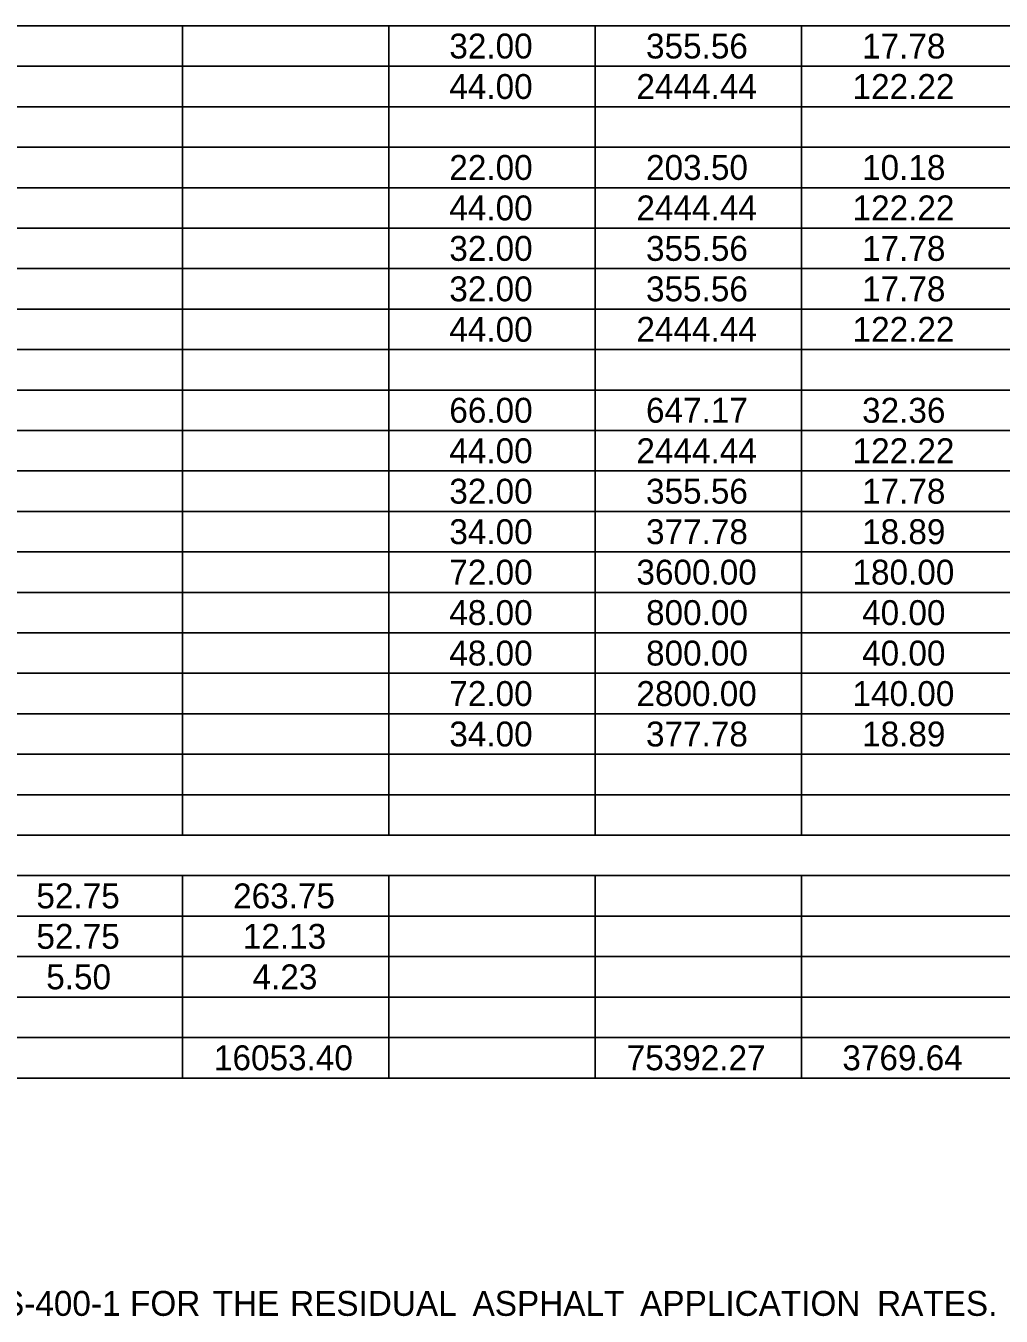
# Model space of a CAD drawing. Extents: x 977434 to 989596, y 1525697 to 1528336.
# Drawn here: x 983038 to 983226, y 1527564.5 to 1527813.2 of the extents above; entities that cross this region are included whole.
import ezdxf

# ---------------------------------------------------------------- set-up
doc = ezdxf.new("R2010")
doc.units = 0
doc.layers.add('Default', color=7, linetype='Continuous')

msp = doc.modelspace()

# ---------------------------------------------------------------- linework, layer by layer
at = {"layer": 'Default'}
for p, q in [((982704.74, 1527813.24), (984062.72, 1527813.24)), ((983068.22, 1527657.24), (983068.22, 1527813.24)), ((983068.22, 1527657.24), (983068.22, 1527813.24)), ((983108, 1527657.24), (983108, 1527813.24)), ((983108, 1527657.24), (983108, 1527813.24)), ((983147.78, 1527657.24), (983147.78, 1527813.24)), ((983147.78, 1527657.24), (983147.78, 1527813.24)), ((983187.56, 1527657.24), (983187.56, 1527813.24)), ((983187.56, 1527657.24), (983187.56, 1527813.24)), ((982704.74, 1527805.44), (984062.72, 1527805.44)), ((982704.74, 1527797.64), (984062.72, 1527797.64)), ((982704.74, 1527789.84), (984062.72, 1527789.84)), ((982704.74, 1527782.04), (984062.72, 1527782.04)), ((982704.74, 1527774.24), (984062.72, 1527774.24)), ((982704.74, 1527766.44), (984062.72, 1527766.44)), ((982704.74, 1527758.64), (984062.72, 1527758.64)), ((982704.74, 1527750.84), (984062.72, 1527750.84)), ((982704.74, 1527743.04), (984062.72, 1527743.04)), ((982704.74, 1527735.24), (984062.72, 1527735.24)), ((982704.74, 1527727.44), (984062.72, 1527727.44)), ((982704.74, 1527719.64), (984062.72, 1527719.64)), ((982704.74, 1527711.84), (984062.72, 1527711.84)), ((982704.74, 1527704.04), (984062.72, 1527704.04)), ((982704.74, 1527696.24), (984062.72, 1527696.24)), ((982704.74, 1527688.44), (984062.72, 1527688.44)), ((982704.74, 1527680.64), (984062.72, 1527680.64)), ((982704.74, 1527672.84), (984062.72, 1527672.84)), ((982704.74, 1527665.04), (984062.72, 1527665.04)), ((982704.74, 1527657.24), (983108, 1527657.24)), ((982704.74, 1527657.24), (984062.72, 1527657.24)), ((983108, 1527657.24), (983346.68, 1527657.24)), ((982704.74, 1527649.44), (984062.72, 1527649.44)), ((983068.22, 1527610.44), (983068.22, 1527649.44)), ((983068.22, 1527610.44), (983068.22, 1527649.44)), ((983108, 1527610.44), (983108, 1527649.44)), ((983108, 1527610.44), (983108, 1527649.44)), ((983147.78, 1527610.44), (983147.78, 1527649.44)), ((983147.78, 1527610.44), (983147.78, 1527649.44)), ((983187.56, 1527610.44), (983187.56, 1527649.44)), ((983187.56, 1527610.44), (983187.56, 1527649.44)), ((982704.74, 1527641.64), (984062.72, 1527641.64)), ((982704.74, 1527633.84), (984062.72, 1527633.84)), ((982704.74, 1527626.04), (984062.72, 1527626.04)), ((982704.74, 1527618.24), (984062.72, 1527618.24)), ((982704.74, 1527610.44), (984062.72, 1527610.44))]:
    msp.add_line(p, q, dxfattribs=at)

# ---------------------------------------------------------------- texts
for s, p in [('32.00', (983119.66, 1527806.94)), ('355.56', (983157.57, 1527806.94)), ('17.78', (983199.21, 1527806.94)), ('44.00', (983119.66, 1527799.14)), ('2444.44', (983155.72, 1527799.14)), ('122.22', (983197.38, 1527799.14)), ('22.00', (983119.66, 1527783.54)), ('203.50', (983157.58, 1527783.54)), ('10.18', (983199.21, 1527783.54)), ('44.00', (983119.66, 1527775.74)), ('2444.44', (983155.72, 1527775.74)), ('122.22', (983197.38, 1527775.74)), ('32.00', (983119.66, 1527767.94)), ('355.56', (983157.57, 1527767.94)), ('17.78', (983199.21, 1527767.94)), ('32.00', (983119.66, 1527760.14)), ('355.56', (983157.57, 1527760.14)), ('17.78', (983199.21, 1527760.14)), ('44.00', (983119.66, 1527752.34)), ('2444.44', (983155.72, 1527752.34)), ('122.22', (983197.38, 1527752.34)), ('66.00', (983119.66, 1527736.74)), ('647.17', (983157.57, 1527736.74)), ('32.36', (983199.21, 1527736.74)), ('44.00', (983119.66, 1527728.94)), ('2444.44', (983155.72, 1527728.94)), ('122.22', (983197.38, 1527728.94)), ('32.00', (983119.66, 1527721.14)), ('355.56', (983157.57, 1527721.14)), ('17.78', (983199.21, 1527721.14)), ('34.00', (983119.66, 1527713.34)), ('377.78', (983157.57, 1527713.34)), ('18.89', (983199.21, 1527713.34)), ('72.00', (983119.66, 1527705.54)), ('3600.00', (983155.72, 1527705.54)), ('180.00', (983197.36, 1527705.54)), ('48.00', (983119.66, 1527697.74)), ('800.00', (983157.58, 1527697.74)), ('40.00', (983199.22, 1527697.74)), ('48.00', (983119.66, 1527689.94)), ('800.00', (983157.58, 1527689.94)), ('40.00', (983199.22, 1527689.94)), ('72.00', (983119.66, 1527682.14)), ('2800.00', (983155.72, 1527682.14)), ('140.00', (983197.36, 1527682.14)), ('34.00', (983119.66, 1527674.34)), ('377.78', (983157.57, 1527674.34)), ('18.89', (983199.21, 1527674.34)), ('52.75', (983040.08, 1527643.14)), ('263.75', (983077.99, 1527643.14)), ('52.75', (983040.08, 1527635.34)), ('12.13', (983079.87, 1527635.34)), ('5.50', (983041.97, 1527627.54)), ('4.23', (983081.74, 1527627.54)), ('16053.40', (983074.3, 1527611.94)), ('75392.27', (983153.84, 1527611.94)), ('3769.64', (983195.41, 1527611.94)), (' SS-400-1', (983027.39, 1527564.6)), (' FOR', (983056.34, 1527564.6)), (' THE', (983072.27, 1527564.6)), (' RESIDUAL', (983087.19, 1527564.6)), (' ASPHALT', (983122.36, 1527564.6)), (' APPLICATION', (983154.66, 1527564.6)), (' RATES.', (983200.32, 1527564.6))]:
    msp.add_text(s, height=4.8, dxfattribs=at).set_placement(p)

doc.saveas('drawing.dxf')
